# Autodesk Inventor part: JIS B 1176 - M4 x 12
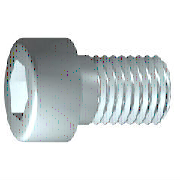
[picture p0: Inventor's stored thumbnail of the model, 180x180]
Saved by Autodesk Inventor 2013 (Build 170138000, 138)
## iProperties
Created: 2012-02
Part Number: JIS B 1176 - M4 x 12
Material: 강철, 연강
Description: 원통형 머리 캡 나사
Document SubType Name: Modeling
Standard: JIS B 1176
Designer: mdu-01
Standards Organization: JIS
Language: ko-KR
Size Designation: M4 x 12
Categories: <MemberInstance><Categories><Category DisplayName="조임쇠" InternalName="e4da775c-781d-43d5-af7c-5136215cf5a6" Mnemonic="FSTN"><Category DisplayName="볼트" InternalN
Density: 1 g/cm^3
IsCustomPart: 1
Author: mdu-01
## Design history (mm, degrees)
sketch "스케치1"
  geometry: L1 (-1, 0)-(12, 0); L2 (12, 0)-(12, 2); L3 (12, 2)-(1.75, 2); L4 (1.75, 2)-(1.32, 2); L5 (1.32, 2)-(0, 2); L6 (0, 2)-(0, 3.5); L7 (0, 3.5)-(-4, 3.5); L8 (-4, 3.5)-(-4, 1.732); L9 (-4, 1.732)-(-2, 1.732); L10 (-2, 1.732)-(-1, 0); L11 (-7.2, 0)-(15.2, 0) reference; L12 (0, -0.7)-(0, 4.2) reference; L13 (1.75, 2)-(0, 2)
  constraints: 22 end point, 6 parallel, 2 collinear, 2 perpendicular, 1 horizontal, 1 point on line
  dimensions: "d1" = 10.25 distance from line of L3.end L2 (= GEL); "d2" = 0.42952 distance of L4.end L3.end (computed from GAL); "d3" = 4 distance between parallel lines of L8 L6 (= KOH); "d4" = 2 distance of L8.end L9.end (= INTI); "d5" = 60 deg angle of L10 L1; "d6" = 4 diameter of L3 L1 (= GD); "d7" = 4 diameter of L5 L1 (= BDM); "d8" = 3.4641 diameter of L9 L1 (= 1.1547 x SW); "d9" = 7 diameter of L7 L1 (= KOD); "d26" = 12 distance between parallel lines of L12 L2 (= NLG)
revolve "본체" sketch "스케치1" stored, may be unused: angle "d10" = 90 deg
sketch "스케치2"
  geometry: L1 (0, -4.9)-(0, 4.9) reference; L2 (-4.9, 0)-(4.9, 0) reference; L3 (1.732, 0)-(0.866, -1.5); L4 (0.866, -1.5)-(-0.866, -1.5); L5 (-0.866, -1.5)-(-1.732, 0); L6 (-1.732, 0)-(-0.866, 1.5); L7 (-0.866, 1.5)-(0.866, 1.5); L8 (0.866, 1.5)-(1.732, 0); 2 further points
  constraints: 12 end point, 1 coincident, 1 horizontal alignment, 1 point on line, 12 other
extrude "슬롯" join sketch "스케치2" stored distance "d11" = 10; taper "d12" = 0 deg
workplane "Work Plane1"
fillet "Fillet2" dims "d30" = 0.1 (= R)
body "Solid1"
fillet "모깎기1" dims "d17" = 0.4 (= RR)
feature "스레드" dims "d13" = 10.25 (= GEL), "d14" = 0
chamfer "모따기1" distance "d15" = 0.42941 (= -0.5 x SPD + 0.5 x GD); stored, may be unused: second distance "d16" = 0.42941 (= GUL), angle "d27" = 45 deg
other parameters: "GD" = 4 (= NND) [user parameter; used in 2 equation terms], "NLG" = 12 [user parameter; used in 1 equation term], "GEL" = 10.25 [user parameter; used in 2 equation terms], "KOD" = 7 [user parameter; used in 1 equation term], "KOH" = 4 [user parameter; used in 1 equation term], "INTI" = 2 [user parameter; used in 1 equation term], "GAL" = 0.42941 (= 0.61345 x PTC) [user parameter; used in 1 equation term], "GUL" = 0.42941 (= 0.61345 x PTC) [user parameter; used in 1 equation term], "BDM" = 4 (= NND) [user parameter; used in 1 equation term], "SW" = 3 [user parameter; used in 2 equation terms], "RR" = 0.4 [user parameter; used in 1 equation term], "SPD" = 3.14117 (= NND - 1.2269 x PTC) [user parameter; used in 1 equation term], "d19" = 0, "d28" = 0, "d29" = 0, "R" = 0.1 [user parameter; used in 1 equation term], "PHH" = 0.2 [user parameter], "GD1" = 3.14117 (= THREADDIA - 1.2269 x PTC) [user parameter], "THREADDIA" = 4 [user parameter; used in 1 equation term], "FAWI" = 45 deg [user parameter], "TPU" = 14.28571 (computed from PTC) [user parameter], "PTC" = 0.7 [user parameter; used in 5 equation terms], "NND" = 4 [user parameter; used in 3 equation terms], "TOA" = 30 deg [user parameter], "E0" = 3.465 (= 1.155 x SW) [user parameter]
